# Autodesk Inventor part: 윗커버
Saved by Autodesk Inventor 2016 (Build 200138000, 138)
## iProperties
Created: 2024-08
Part Number: 윗커버
Material: 일반
Document SubType Name: Modeling
Designer: pc-2
Density: 1 g/cm^3
Appearance: 기본값
Author: jhkim
Sending System: Autodesk Inventor 2025
Preprocessor: ST-DEVELOPER v20
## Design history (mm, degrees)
node "윗커버1"
node "솔리드2"
node "솔리드1"
